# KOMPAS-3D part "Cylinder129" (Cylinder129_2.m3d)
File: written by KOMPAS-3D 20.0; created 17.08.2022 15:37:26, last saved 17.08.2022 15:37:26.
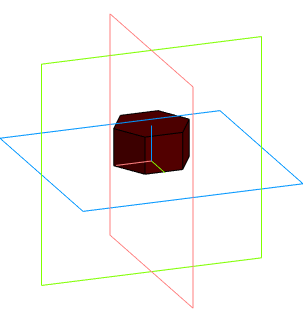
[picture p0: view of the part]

Document properties: Автор: artemsv220@gmail.com; Полное имя файла: \\192.168.2.25\новая общая папка\Медиа\Светильники\Кашпо\Кашпо и вазоны\DWG\Cylinder129_2.m3d

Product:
- Part/product: Cylinder129

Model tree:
1. Операция без истории:1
